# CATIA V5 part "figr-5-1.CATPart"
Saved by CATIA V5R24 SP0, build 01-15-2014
Part number: Part1
Bounding box of the stored display mesh (mm): x -23 to 23, y -104 to 104, z 0 to 68
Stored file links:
  D:\KAVITA\CATIA V5-6R2014 Project_ Kavita\CATIA V5-6R2014_partfiles\Partfiles\c05_catia_v5-6r2014_prt\figr-5-1.CATPart
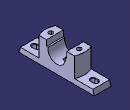
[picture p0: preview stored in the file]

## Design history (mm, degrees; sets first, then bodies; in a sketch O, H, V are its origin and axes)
Sketch1 on yz-plane, origin (0, 0, 0), H (0, 1, 0), V (0, 0, 1)
  line L1 (0, 0) -> (104, 0)
  point P1 (104, 0)
  line L2 (104, 0) -> (100, 14)
  point P2 (100, 14)
  line L3 (100, 14) -> (54, 14)
  point P3 (54, 14)
  line L4 (54, 14) -> (54, 68)
  point P4 (54, 68)
  line L5 (54, 68) -> (28, 68)
  point P5 (28, 68)
  line L6 (28, 68) -> (28, 52)
  point P6 (28, 52)
  line L7 (28, 52) -> (23.6643, 52)
  axis line L8 (0, 0) -> (0, 150)
  point P8 (0, 0)
  construction line L9 through (0, 0) direction (-1, 0)
  construction line L10 through (0, 0) direction (0, 1)
  point P13 (-104, 0)
  point P14 (-100, 14)
  point P15 (-54, 14)
  point P16 (-54, 68)
  point P17 (-28, 68)
  point P18 (-28, 52)
  line L11 (0, 0) -> (-104, 0)
  line L12 (-104, 0) -> (-100, 14)
  line L13 (-100, 14) -> (-54, 14)
  line L14 (-54, 14) -> (-54, 68)
  line L15 (-54, 68) -> (-28, 68)
  line L16 (-28, 68) -> (-28, 52)
  line L17 (-28, 52) -> (-23.6643, 52)
  arc A1 centre (0, 48) radius 24 from (-23.6643, 52) to (23.6643, 52) ccw
  point P19 (0, 48)
  point P20 (13.2665, 68)
  distance P1 P13 = 208
  length L2 V = 14
  length L2 H = 4
  distance L4 L14 = 108
  distance L16 L6 = 56
  distance L1 L5 = 68
  length L6 = 16
  distance P19 L7 = 4
  radius A1 = 24
  horizontal: L1 H, L3 H, L5 H, L7 H
  vertical: L4 V, L6 V, L8 V
  symmetry: O P8 L8, H L9 L8, V L10 L8, P1 P13 L8, P2 P14 L8, P3 P15 L8, P4 P16 L8, P5 P17 L8, P6 P18 L8, L1 L11 L8, L2 L12 L8, L3 L13 L8, L4 L14 L8, L5 L15 L8, L6 L16 L8, L7 L17 L8
  coincidence: P19 L8, A1 P20, P20 L5, O P8
Pad1: profile Sketch1, direction (1, 0, 0), length 23, mirrored extent
Body1 (main body)
  Sketch2 on face of Pad1, origin (0, 0, 68), H (1, 0, 0), V (0, 1, 0)
    arc A1 centre (0, 0) radius 54 from (-23, 48.8569) to (23, 48.8569) cw
    point P1 (0, 0)
    point P2 (-23, 48.8569)
    point P3 (23, 48.8569)
    reference projected line E1 (23, 54) -> (23, 28) from edge [face of Pad1 | face of Pad1]
    reference projected line E2 (-23, 54) -> (-23, 28) from edge [face of Pad1 | face of Pad1]
    reference projected line E3 (-23, 54) -> (23, 54) from edge [face of Pad1 | face of Pad1]
    axis line L1 (-38.3733, 0) -> (57.2772, 0)
    point P4 (-38.3733, 0)
    point P6 (-23, -48.8569)
    point P7 (23, -48.8569)
    arc A2 centre (0, 0) radius 54 from (-23, -48.8569) to (23, -48.8569) ccw
    line L2 (-23, 48.8569) -> (-23, -48.8569)
    point P9 (-23, -48.8569)
    line L3 (23, 48.8569) -> (23, -48.8569)
    coincidence: P3 E1, P2 E2, P1 O, P4 H, P9 P6
    tangency: A1 E3
    horizontal: L1 H
    symmetry: P2 P6 L1, P3 P7 L1, A1 A2 L1
    vertical: L2 V, L3 V
  Pocket1: profile Sketch2, direction (0, 0, -1), up to face of Pad1, outer side
  Sketch3 on face of Pad1, origin (0, 0, 0), H (1, 0, 0), V (0, -1, 0)
    line L1 (-13, 52) -> (13, 52)
    line L2 (13, 52) -> (13, 26)
    line L3 (13, 26) -> (-13, 26)
    line L4 (-13, 26) -> (-13, 52)
    axis line L5 (13, 26) -> (-13, 52)
    point P5 (0, 39)
    length L2 = 26
    length L1 = 26
    distance P5 O H = 0
    distance P5 H = 39
    horizontal: L1 H, L3 H
    vertical: L2 V, L4 V
    midpoint: P5 L5
  Pocket2: profile Sketch3, direction (0, 0, 1), length 10
  Sketch4 on face of Pocket2, origin (0, -39, 10), H (1, 0, 0), V (0, -1, 0)
    point P1 (0, 0)
    reference projected point E1 (0, 0) from vertex of Sketch7
    coincidence: E1 P1
  Hole1: placed by Sketch4, at (0, -39, 10) direction (0, 0, 1), diameter 12, through (limit type 3)
  Sketch5 on face of Pad1, origin (0, 0, 14), H (1, 0, 0), V (0, 1, 0)
    construction line L1 (0, -85) -> (0, -77)
    point P1 (0, -85)
    line L2 (-6, -85) -> (-6, -77)
    line L3 (6, -77) -> (6, -85)
    arc A1 centre (0, -77) radius 6 from (-6, -77) to (6, -77) cw
    arc A2 centre (0, -85) radius 6 from (6, -85) to (-6, -85) cw
    point P7 (0, -81)
    distance A1 A2 = 20
    distance L3 L2 = 12
    distance P7 H = 81
    coincidence: P1 V
    vertical: L1 V
    tangency: A1 L2, A2 L2, A1 L3, A2 L3
    parallelism: L1 L2
    midpoint: P7 L1
  Pocket3: profile Sketch5, direction (0, 0, -1), through (limit type 3)
  Chamfer1: length 1.5, angle 45, on 1 edge
  Sketch6 on yz-plane, origin (0, 0, 0), H (0, 1, 0), V (0, 0, 1)
    axis line L1 (0, 0) -> (0, 35.393)
    reference projected arc E1 centre (0, 48) radius 24 from (-23.6643, 52) to (23.6643, 52) ccw from edge [face of Pad1 | face of Pad1]
    projected arc E2 centre (0, 48) radius 24 from (0, 24) to (4, 24.3357) ccw from edge [face of Pad1 | face of Pad1]
    point P4 (4, 24.3357)
    line L2 (4, 24.3357) -> (4, 16)
    line L3 (4, 16) -> (0, 16)
    point P6 (0, 16)
    line L4 (0, 16) -> (0, 24)
    point P7 (0, 24)
    point P8 (0, 24)
    radius about axis L2 L1 = 4
    distance E1 L3 = 8
    vertical: L1 V, L2 V, L4 V
    coincidence: P4 E1, P6 L1, P7 E1, L1 P8, P7 P8
    horizontal: L3 H
  Groove1: profile Sketch6, axis Sketch6.L1, angle 360
  Mirror1: of Pocket2, Sketch3, Hole1, Pocket3, Sketch5, Chamfer1, about zx-plane
  Sketch7 on face of Pocket2, origin (0, 0, 10), H (1, 0, 0), V (0, -1, 0)
    point P1 (0, 39)
    axis line L1 (13, 26) -> (-13, 52)
    point P2 (13, 26)
    point P3 (-13, 52)
    reference projected point E1 (13, 26) from vertex [face of Pocket2 | face of Pad1 | face of Pocket2]
    reference projected point E2 (-13, 52) from vertex [face of Pocket2 | face of Pad1 | face of Pocket2]
    coincidence: P1 V, L1 P1, E1 P2, P3 E2
    midpoint: P1 L1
